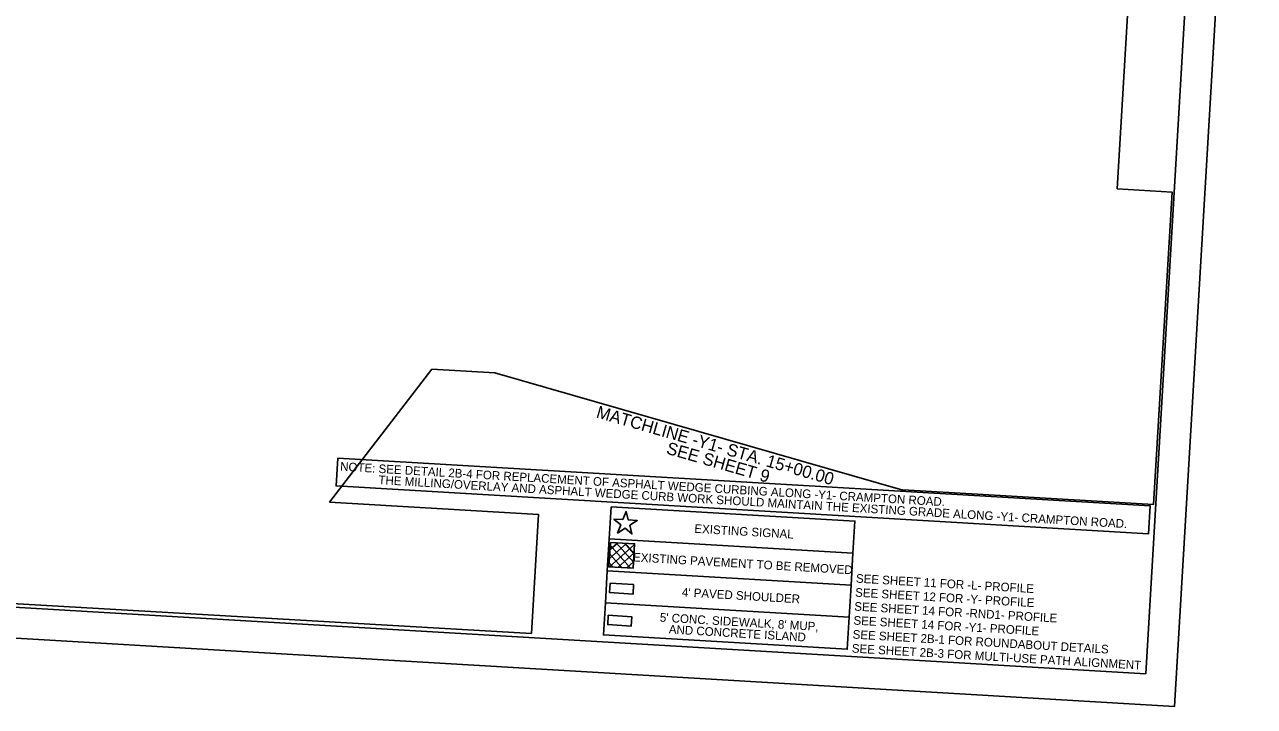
# Model space of a CAD drawing. Extents: x 2010737 to 2012732, y 444258 to 445456.
# Drawn here: x 2011735 to 2012732, y 444258 to 444812 of the extents above; entities that cross this region are included whole.
import ezdxf

# ---------------------------------------------------------------- set-up
doc = ezdxf.new("R2010")
doc.units = 0
for name, color, linetype in [('Exist PHM Road to be Removed Shape', 7, 'Continuous'), ('Matchline', 7, 'Continuous'), ('Matchline Text', 7, 'Continuous'), ('Old_Level_1', 7, 'Continuous'), ('Prop DSN Text', 7, 'Continuous'), ('Prop RDY Traffic Signal CELL', 7, 'Continuous'), ('Prop Shade Light', 7, 'Continuous'), ('Prop Shade Medium', 7, 'Continuous'), ('Sheet Clip Boundary CELL', 7, 'Continuous'), ('Sheet Plan And Profile CELL', 7, 'Continuous'), ('Sheet Plot Border Outside CELL', 7, 'Continuous')]:
    doc.layers.add(name, color=color, linetype=linetype)

msp = doc.modelspace()

# ---------------------------------------------------------------- linework, layer by layer
at = {"layer": 'Exist PHM Road to be Removed Shape'}
for p, q in [((2012208.96, 444371.58), (2012229.35, 444389.69)), ((2012209, 444378.3), (2012222.84, 444390.6)), ((2012209.22, 444381.98), (2012218.99, 444370.98)), ((2012209.42, 444385.36), (2012215.79, 444391.02)), ((2012209.63, 444389.04), (2012226.05, 444370.57)), ((2012214.5, 444391.09), (2012228.5, 444375.33)), ((2012216.02, 444371.16), (2012228.93, 444382.63)), ((2012221.55, 444390.68), (2012228.92, 444382.39)), ((2012228.61, 444390.26), (2012229.33, 444389.45)), ((2012208.8, 444374.92), (2012211.93, 444371.4)), ((2012223.08, 444370.74), (2012228.52, 444375.58))]:
    msp.add_line(p, q, dxfattribs=at)
msp.add_lwpolyline([(2012209.77, 444391.37), (2012229.38, 444390.22), (2012228.21, 444370.44), (2012208.6, 444371.6)], close=True, dxfattribs=at)
at = {"layer": 'Matchline'}
msp.add_line((2012116.09, 444528.98), (2012447, 444433.71), dxfattribs=at)
at = {"layer": 'Old_Level_1'}
for p, q in [((2012207.25, 444368.35), (2012205.71, 444342.34)), ((2012405.1, 444356.69), (2012403.56, 444330.67))]:
    msp.add_line(p, q, dxfattribs=at)
for points in [[(2011988.56, 444459.83), (2012647.77, 444420.97), (2012646.43, 444398.38), (2011987.23, 444437.24)], [(2012210.31, 444420.38), (2012408.16, 444408.72), (2012406.63, 444382.7), (2012208.78, 444394.36)], [(2012208.78, 444394.36), (2012406.63, 444382.7), (2012405.1, 444356.69), (2012207.25, 444368.35)], [(2012205.71, 444342.34), (2012403.56, 444330.67), (2012402.03, 444304.66), (2012204.18, 444316.32)]]:
    msp.add_lwpolyline(points, close=True, dxfattribs=at)
at = {"layer": 'Prop RDY Traffic Signal CELL'}
msp.add_lwpolyline([(2012219.91, 444409.83), (2012212.71, 444410.25), (2012218.28, 444405.68), (2012215.65, 444398.96), (2012221.74, 444402.85), (2012227.32, 444398.27), (2012225.49, 444405.26), (2012231.57, 444409.15), (2012224.36, 444409.57), (2012222.54, 444416.56), (2012219.91, 444409.83)], dxfattribs=at)
at = {"layer": 'Prop Shade Light'}
msp.add_lwpolyline([(2012209.64, 444358.22), (2012228.66, 444357.1), (2012228.21, 444349.49), (2012209.19, 444350.62)], close=True, dxfattribs=at)
at = {"layer": 'Prop Shade Medium'}
msp.add_lwpolyline([(2012208.11, 444332.21), (2012227.12, 444331.09), (2012226.67, 444323.48), (2012207.66, 444324.6)], close=True, dxfattribs=at)
at = {"layer": 'Sheet Clip Boundary CELL'}
msp.add_lwpolyline([(2011147.85, 444375), (2012145.7, 444317.47), (2012151.4, 444414.1), (2011981.99, 444424.08), (2012065.05, 444531.98), (2012116.09, 444528.98), (2012447, 444433.71), (2012447.13, 444434.15), (2012512.37, 444430.3), (2012650.6, 444422.19), (2012665.49, 444675.78), (2012620.99, 444678.39), (2012629.52, 444823.68), (2012643.65, 445063.27), (2012648.58, 445153.9), (2012495.5, 445162.92), (2012502.28, 445278.05), (2012302.58, 445289.82), (2012278.52, 445262.33), (2012176.97, 445268.45), (2011765.99, 445293.2), (2011771.61, 445387.92), (2011477.93, 445405.24)], dxfattribs=at)
at = {"layer": 'Sheet Plan And Profile CELL'}
msp.add_lwpolyline([(2012705.91, 445332.85), (2011208.51, 445421.12), (2011146.72, 444372.94), (2012644.12, 444284.67)], close=True, dxfattribs=at)
at = {"layer": 'Sheet Plot Border Outside CELL'}
msp.add_lwpolyline([(2010970.55, 444358.28), (2012667.61, 444258.24), (2012732.34, 445356.33), (2011035.28, 445456.37)], close=True, dxfattribs=at)

# ---------------------------------------------------------------- texts
at = {"layer": 'Matchline Text'}
for s, p in [('MATCHLINE -Y1- STA. 15+00.00', (2012197.67, 444492.91)), ('SEE SHEET 9', (2012254.52, 444463.53))]:
    msp.add_text(s, height=10, rotation=343.94025, dxfattribs=at).set_placement(p)
at = {"layer": 'Prop DSN Text'}
for s, p in [('NOTE: SEE DETAIL 2B-4 FOR REPLACEMENT OF ASPHALT WEDGE CURBING ALONG -Y1- CRAMPTON ROAD.', (2011990.4, 444449.66)), ('THE MILLING/OVERLAY AND ASPHALT WEDGE CURB WORK SHOULD MAINTAIN THE EXISTING GRADE ALONG -Y1- CRAMPTON ROAD.', (2012021.45, 444438.77)), ('EXISTING SIGNAL', (2012277.82, 444399.18)), ('EXISTING PAVEMENT TO BE REMOVED', (2012228.06, 444376.01)), ('SEE SHEET 11 FOR -L- PROFILE', (2012408.88, 444358.77)), ("4' PAVED SHOULDER", (2012267.66, 444347.57)), ('SEE SHEET 12 FOR -Y- PROFILE', (2012408.22, 444347.41)), ('SEE SHEET 14 FOR -RND1- PROFILE', (2012407.55, 444336.06)), ("5' CONC. SIDEWALK, 8' MUP,", (2012249.78, 444327.11)), ('AND CONCRETE ISLAND', (2012257.07, 444317.49)), ('SEE SHEET 14 FOR -Y1- PROFILE', (2012406.88, 444324.7)), ('SEE SHEET 2B-1 FOR ROUNDABOUT DETAILS', (2012406.21, 444313.34)), ('SEE SHEET 2B-3 FOR MULTI-USE PATH ALIGNMENT', (2012405.54, 444301.99))]:
    msp.add_text(s, height=7, rotation=356.62643, dxfattribs=at).set_placement(p)

doc.saveas('drawing.dxf')
